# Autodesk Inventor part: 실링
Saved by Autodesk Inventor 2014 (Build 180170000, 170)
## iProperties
Created: 2025-10
Part Number: 실링
Material: 일반
Document SubType Name: Modeling
Designer: dg
Density: 1 g/cm^3
Appearance: 기본값
Author: dg
Author: jhkim
Creation Date: 2025-10-01
Sending System: Autodesk Inventor 2026
Preprocessor: ST-DEVELOPER v20.1
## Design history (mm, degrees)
node "실링1"
node "솔리드1"
node "기준1"
